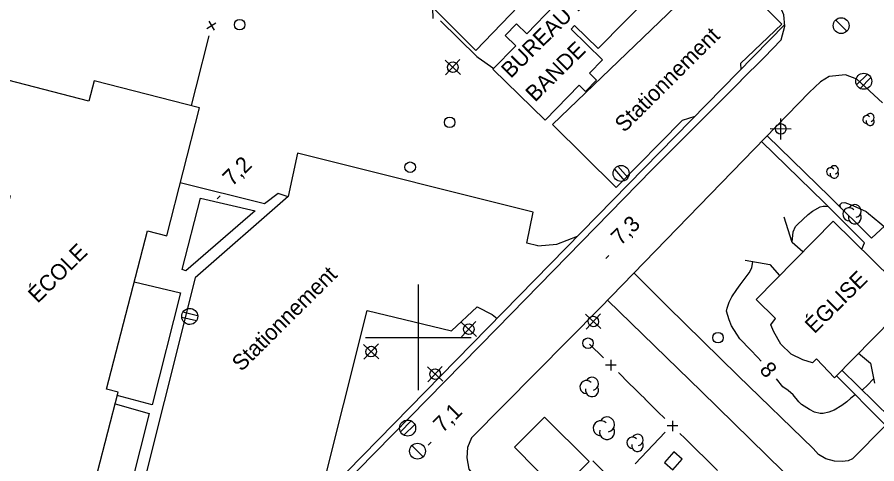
# Model space of a CAD drawing. Extents: x 381879 to 384696, y 5564785 to 5567594.
# Drawn here: x 382924 to 383086.9, y 5565376 to 5565460.7 of the extents above; entities that cross this region are included whole.
import ezdxf

# ---------------------------------------------------------------- set-up
doc = ezdxf.new("R2010")
doc.units = 0
for name, color, linetype in [('Niveau 2', 7, 'Continuous'), ('Niveau 21', 7, 'Continuous'), ('Niveau 22', 7, 'Continuous'), ('Niveau 3', 7, 'Continuous'), ('Niveau 31', 7, 'Continuous'), ('Niveau 36', 7, 'Continuous'), ('Niveau 37', 7, 'Continuous'), ('Niveau 44', 7, 'Continuous'), ('Niveau 52', 7, 'Continuous'), ('Niveau 61', 7, 'Continuous')]:
    doc.layers.add(name, color=color, linetype=linetype)

msp = doc.modelspace()

# ---------------------------------------------------------------- linework, layer by layer
at = {"layer": 'Niveau 2'}
for points in [[(383080.12, 5565424.51), (383079.91, 5565425.12), (383080.28, 5565425.51), (383080.83, 5565425.54), (383081.34, 5565425.39), (383082.38, 5565424.96), (383084.92, 5565423.85), (383085.37, 5565423.49), (383087.48, 5565421.73), (383088.3, 5565420.98)], [(383070.85, 5565418.07), (383071.04, 5565420.01), (383071.51, 5565420.99), (383071.89, 5565421.37), (383073.9, 5565423.27), (383074.74, 5565423.89), (383076.2, 5565424.75), (383076.72, 5565424.86), (383077.27, 5565424.87), (383077.71, 5565424.77)], [(383064.99, 5565395.48), (383064.27, 5565396.26), (383062.96, 5565397.61), (383060.98, 5565399.73), (383060.38, 5565400.59), (383059.39, 5565402.2), (383058.91, 5565403.32), (383058.44, 5565404.98), (383058.54, 5565405.56), (383058.93, 5565406.66), (383059.46, 5565407.7), (383060.36, 5565409.07), (383061.03, 5565409.93), (383062.72, 5565412.22), (383063.2, 5565413.16), (383063.44, 5565414.38)], [(383082.84, 5565389.11), (383082, 5565388.49), (383081.25, 5565387.8), (383080.27, 5565387.08), (383078.86, 5565386.23), (383077.81, 5565385.83), (383076.73, 5565385.57), (383076.17, 5565385.57), (383075.11, 5565385.85), (383074.15, 5565386.35), (383072.62, 5565387.3), (383072.16, 5565387.79), (383071.03, 5565389.11), (383070.12, 5565389.92), (383069.13, 5565390.64), (383067.87, 5565392.15)], [(383086.3, 5565392.13), (383085.11, 5565390.88), (383084.24, 5565390.1), (383084.13, 5565390.03)]]:
    msp.add_lwpolyline(points, dxfattribs=at)
at = {"layer": 'Niveau 21'}
for points in [[(383065.57, 5565453.03), (383068.81, 5565456.41), (383069.5, 5565458.99), (383069.32, 5565461.15), (383068.44, 5565463.02), (383065.61, 5565465.9), (383019.96, 5565510.43), (382982.18, 5565547.34), (382977.34, 5565552.41)], [(383061.16, 5565448.67), (383065.57, 5565453.03)], [(382945.1, 5565267.4), (382957.85, 5565280.55), (382958.51, 5565283.24), (382958.26, 5565285.83), (382957.71, 5565287.93), (382956.39, 5565289.74), (382926.01, 5565319.42), (382929.66, 5565323.08), (382936.92, 5565330.06), (382939.18, 5565328.45), (382942.16, 5565328.43), (382944.61, 5565329.79), (382952.32, 5565337.6), (382975.41, 5565361.41), (383014.89, 5565401.7), (383044.36, 5565431.82), (383061.2, 5565448.71)], [(383087.97, 5565444.43), (383083.16, 5565448.92), (383080.99, 5565449.74), (383077.87, 5565449.44), (383076.23, 5565448.4), (383074.1, 5565446.4), (383034.53, 5565405.66), (383010.08, 5565380.98), (383009.31, 5565379.13), (383009.17, 5565377.16), (383009.57, 5565375.02), (383010.97, 5565373.31), (383012.56, 5565371.48), (383015.67, 5565368.65)]]:
    msp.add_lwpolyline(points, dxfattribs=at)
at = {"layer": 'Niveau 22'}
for points in [[(382963.59, 5565351.22), (382971.66, 5565359.43), (383069.46, 5565459.27), (383069.48, 5565459.29)], [(383084.07, 5565416.7), (383084.57, 5565417.91), (383076.94, 5565425.54), (383065.08, 5565437.11)], [(383100.11, 5565432.98), (383089.28, 5565421.88), (383085.91, 5565418.78), (383077.99, 5565426.62), (383066.12, 5565438.18)], [(382975.32, 5565426.64), (382973.41, 5565427.27), (382970.86, 5565425.3), (382954.88, 5565429.29)], [(382958.73, 5565426.39), (382969.06, 5565423.95), (382955.95, 5565412.59), (382955.22, 5565412.83), (382958.73, 5565426.39)], [(382946.15, 5565410.53), (382954.93, 5565408.43), (382949.52, 5565387.24), (382942.9, 5565388.95)], [(383080.3, 5565393.76), (383089.6, 5565384.7)], [(383088.42, 5565383.48), (383079.27, 5565392.71)], [(382942.5, 5565387.41), (382949, 5565385.54), (382943.86, 5565365.3), (382937.16, 5565366.85)]]:
    msp.add_lwpolyline(points, dxfattribs=at)
at = {"layer": 'Niveau 3'}
for p, q in [((382961.89, 5565426.23), (382962.46, 5565426.8)), ((383035.54, 5565414.96), (383036.11, 5565415.53)), ((383001.85, 5565379.57), (383002.42, 5565380.14))]:
    msp.add_line(p, q, dxfattribs=at)
at = {"layer": 'Niveau 31'}
for points in [[(383027.32, 5565481.58), (383035.55, 5565473.49), (383036.67, 5565474.63), (383040.71, 5565470.66), (383039.57, 5565469.5), (383044.17, 5565464.98), (383034.08, 5565454.72), (383029.62, 5565459.11), (383028.96, 5565458.44), (383034.92, 5565452.57), (383032.45, 5565450.06), (383033.78, 5565448.75), (383031.69, 5565446.62), (383030.49, 5565447.79), (383024.03, 5565441.17), (383014.15, 5565450.82), (383018.48, 5565455.25), (383016.45, 5565457.23), (383018.61, 5565459.44), (383020.54, 5565457.55), (383025.8, 5565462.93), (383017.26, 5565471.28)], [(382958.53, 5565443.51), (382938.53, 5565448.64), (382937.54, 5565444.79), (382903.33, 5565453.59), (382898.94, 5565436.52), (382902.71, 5565435.55), (382901.84, 5565432.17), (382922.64, 5565426.82), (382909.08, 5565374.08), (382937.21, 5565366.85), (382943.07, 5565389.63), (382940.9, 5565390.19), (382948.64, 5565420.18), (382952.3, 5565419.24)], [(383078.66, 5565422.04), (383093.61, 5565407.3), (383078.9, 5565392.33), (383075.49, 5565395.95), (383074.7, 5565395.2), (383072.87, 5565395.73), (383070.67, 5565396.79), (383068.71, 5565398.7), (383067.4, 5565401.02), (383066.83, 5565402.36), (383067.74, 5565403.58), (383064.06, 5565407.19)], [(383018.2, 5565379.2), (383023.9, 5565384.9), (383032.4, 5565376.5), (383026.6, 5565370.7)], [(383048.46, 5565378.31), (383046.66, 5565376.31), (383048.22, 5565374.9), (383050.02, 5565376.9)]]:
    msp.add_lwpolyline(points, close=True, dxfattribs=at)
at = {"layer": 'Niveau 36'}
for p, q in [((383081.24, 5565458.02), (383079.12, 5565460.14)), ((383005.07, 5565452.56), (383007.98, 5565449.84)), ((383005.17, 5565449.75), (383007.89, 5565452.66)), ((383085.13, 5565449.87), (383083.07, 5565447.83)), ((383083.73, 5565447.19), (383085.79, 5565449.23)), ((383068.71, 5565437.5), (383068.72, 5565441.48)), ((383070.71, 5565439.48), (383066.72, 5565439.5)), ((383039.74, 5565430.27), (383037.84, 5565432.46)), ((383037.16, 5565431.85), (383039.06, 5565429.66)), ((382958.16, 5565404.09), (382955.33, 5565404.75)), ((383031.7, 5565404.37), (383034.61, 5565401.65)), ((383031.8, 5565401.56), (383034.52, 5565404.47)), ((382955.14, 5565403.85), (382957.97, 5565403.19)), ((383008.11, 5565402.91), (383011.02, 5565400.19)), ((383008.21, 5565400.1), (383010.93, 5565403.01)), ((382989.6, 5565398.66), (382992.51, 5565395.94)), ((382989.7, 5565395.85), (382992.42, 5565398.76)), ((383001.73, 5565394.39), (383004.64, 5565391.67)), ((383001.83, 5565391.58), (383004.55, 5565394.49)), ((382998.66, 5565384.15), (382996.6, 5565382.11)), ((382997.26, 5565381.47), (382999.32, 5565383.51)), ((383000.92, 5565377.37), (382998.8, 5565379.49))]:
    msp.add_line(p, q, dxfattribs=at)
for centre, radius in [((382966.14, 5565459.26), 1), ((383080.17, 5565459.08), 1.5), ((383084.44, 5565448.53), 1.52), ((383005.95, 5565440.75), 1), ((383068.71, 5565439.5), 1), ((382998.45, 5565432.24), 1), ((383032.17, 5565398.89), 1), ((383056.81, 5565399.94), 1), ((382997.97, 5565382.81), 1.52), ((382999.85, 5565378.43), 1.5)]:
    msp.add_circle(centre, radius, dxfattribs=at)
for centre, major_axis, ratio in [((383006.54, 5565451.2), (-0.048, -0.999), 0.999982), ((383038.45, 5565431.07), (-0.01, 1.52), 0.999986), ((382956.66, 5565403.96), (-0.04, 1.52), 0.999981), ((383033.17, 5565403.01), (-0.048, -0.999), 0.999982), ((383009.58, 5565401.55), (-0.048, -0.999), 0.999982), ((382991.07, 5565397.3), (-0.048, -0.999), 0.999982), ((383003.2, 5565393.03), (-0.048, -0.999), 0.999982)]:
    msp.add_ellipse(centre, major_axis=major_axis, ratio=ratio, dxfattribs=at)
at = {"layer": 'Niveau 37'}
for p, q in [((383002.79, 5565460.41), (383002.78, 5565462.41)), ((382960.26, 5565459.93), (382961.29, 5565458.21)), ((382959.91, 5565458.56), (382961.63, 5565459.59)), ((383037.51, 5565394.72), (383035.5, 5565394.71)), ((383036.5, 5565395.72), (383036.51, 5565393.71)), ((383049.17, 5565383.21), (383047.17, 5565383.2)), ((383048.16, 5565384.21), (383048.18, 5565382.2))]:
    msp.add_line(p, q, dxfattribs=at)
for points in [[(383004.21, 5565460.01), (383011.12, 5565453.2), (383011.36, 5565453.03)], [(382960.28, 5565457.14), (382957.82, 5565447.44)], [(383011.36, 5565453.03), (383014.29, 5565450.96)], [(382957.82, 5565447.44), (382956.93, 5565443.92)], [(383072.91, 5565416.19), (383070.89, 5565417.96), (383069.36, 5565422.77)], [(383061.93, 5565414.65), (383066.61, 5565413.81), (383068.49, 5565411.7)], [(383035.08, 5565396.12), (383032.46, 5565398.7)], [(383083.47, 5565396.98), (383085.7, 5565395.09), (383086.46, 5565391.34)], [(383045.04, 5565386.29), (383043, 5565388.31), (383042.99, 5565388.31), (383042.98, 5565388.33), (383042, 5565389.3), (383041.5, 5565389.78), (383041.49, 5565389.79), (383041.25, 5565390.03), (383040.99, 5565390.29), (383039.99, 5565391.27), (383039.99, 5565391.28), (383037.93, 5565393.31)], [(383046.75, 5565384.61), (383045.42, 5565385.91), (383045.04, 5565386.29)], [(383046.77, 5565382.02), (383041.11, 5565376.06)], [(383056.71, 5565374.78), (383050.52, 5565380.88), (383049.59, 5565381.8)], [(383033.08, 5565376.58), (383037.13, 5565372.62), (383037.5, 5565372.26)]]:
    msp.add_lwpolyline(points, dxfattribs=at)
at = {"layer": 'Niveau 44'}
for centre, radius, start, end in [((383085.01, 5565441.29), 0.754, 44.1153, 269.8039), ((383085.66, 5565441.67), 0.754, 282.2692, 149.7262), ((383085.66, 5565440.91), 0.754, 166.9368, 29.6212), ((383078.18, 5565431.35), 0.788, 44.1153, 269.8039), ((383078.85, 5565431.75), 0.788, 282.2692, 149.7262), ((383078.85, 5565430.96), 0.788, 166.9368, 29.6212), ((383081.69, 5565423.33), 1.22, 44.1153, 269.8039), ((383082.74, 5565423.94), 1.22, 282.2692, 149.7262), ((383082.74, 5565422.72), 1.22, 166.9368, 29.6212), ((383031.86, 5565390.59), 1.23, 44.1153, 269.8039), ((383032.92, 5565391.21), 1.23, 282.2692, 149.7262), ((383032.92, 5565389.98), 1.23, 166.9368, 29.6212), ((383035.78, 5565383.49), 1.42, 282.2692, 149.7262), ((383034.56, 5565382.78), 1.42, 44.1153, 269.8039), ((383035.78, 5565382.07), 1.42, 166.9368, 29.6212), ((383041.54, 5565380.55), 1.08, 282.2692, 149.7262), ((383040.61, 5565380.01), 1.08, 44.1153, 269.8039), ((383041.54, 5565379.46), 1.08, 166.9368, 29.6212)]:
    msp.add_arc(centre, radius, start, end, dxfattribs=at)
at = {"layer": 'Niveau 52'}
for points in [[(383035.68, 5565495.09), (383011.8, 5565471.09), (383018.87, 5565464.21), (383019, 5565462.75), (383010.91, 5565454.34), (382993.05, 5565472.35)], [(383068.93, 5565459.35), (383061.97, 5565466.32), (383059.62, 5565464.2), (383056.94, 5565462.89), (383052.73, 5565462.35), (383050.4, 5565464.35), (383025.45, 5565440.33), (383037.51, 5565428.41), (383050.11, 5565441.18), (383052.46, 5565441.91)], [(383068.93, 5565459.35), (383061.1, 5565451.91), (383061.14, 5565450.78)], [(383022.63, 5565417.33), (383020.54, 5565417.86), (383021.77, 5565423.72), (382977.12, 5565434.88), (382975.33, 5565426.68), (382957.72, 5565411.28), (382945.94, 5565364.4), (382963.54, 5565351.17)], [(383022.63, 5565417.33), (383026.23, 5565417.69), (383030.18, 5565419.17)], [(383123.02, 5565410.41), (383111.6, 5565398.21), (383111.25, 5565398), (383110.85, 5565397.94), (383110.38, 5565398.28), (383107.07, 5565402.01), (383082.29, 5565376.99), (383081.49, 5565376.61), (383080.36, 5565376.46), (383078.89, 5565376.52), (383077.28, 5565376.95), (383075.87, 5565377.8), (383074.85, 5565378.96), (383060.66, 5565392.7), (383047.16, 5565405.92), (383040.88, 5565412.2)], [(383035.85, 5565407.02), (383053.65, 5565389.72), (383069.09, 5565374.65), (383072.03, 5565371.98), (383074.04, 5565370.66), (383075.68, 5565369.9), (383077.84, 5565369.58), (383079.81, 5565369.53), (383082.77, 5565369.84), (383084.78, 5565370.4), (383086.76, 5565371.04), (383088, 5565371.83), (383090.86, 5565374.74), (383109.19, 5565356.9), (383127.51, 5565375.57), (383138.19, 5565386.44), (383135.18, 5565389.09), (383134.99, 5565389.62), (383134.88, 5565389.92), (383135.05, 5565390.15), (383139.44, 5565394.63)], [(382981.35, 5565369.32), (382990.31, 5565405.09), (383006.28, 5565401.22), (383011.18, 5565405.77)], [(383011.18, 5565405.77), (383014, 5565404.32), (383014.92, 5565403.6)]]:
    msp.add_lwpolyline(points, dxfattribs=at)
at = {"layer": 'Niveau 61'}
for points in [[(383000, 5565410), (383000, 5565400), (383000, 5565390)], [(382990, 5565400), (383000, 5565400), (383010, 5565400)]]:
    msp.add_lwpolyline(points, dxfattribs=at)

# ---------------------------------------------------------------- texts
at = {"layer": 'Niveau 2'}
msp.add_text('8', height=3, rotation=311.3009, dxfattribs=at).set_placement((383064.51, 5565393.74))
at = {"layer": 'Niveau 3'}
for s, p in [('7,2  ', (382964.7, 5565428.52)), ('7,3  ', (383038.33, 5565417.28)), ('7,1  ', (383004.6, 5565381.78))]:
    msp.add_text(s, height=3, rotation=44.7717, dxfattribs=at).set_placement(p)
at = {"layer": 'Niveau 31'}
for s, p in [('BUREAU DE', (383017.5, 5565448.95)), ('BANDE', (383022.13, 5565444.49)), ('ÉCOLE', (382927.84, 5565406.33)), ('ÉGLISE', (383075.09, 5565400.55))]:
    msp.add_text(s, height=3, rotation=44.7717, dxfattribs=at).set_placement(p)
at = {"layer": 'Niveau 52'}
for p in [(383039.03, 5565438.7), (382966.46, 5565393.4)]:
    msp.add_text('Stationnement', height=3, rotation=44.7717, dxfattribs=at).set_placement(p)

doc.saveas('drawing.dxf')
